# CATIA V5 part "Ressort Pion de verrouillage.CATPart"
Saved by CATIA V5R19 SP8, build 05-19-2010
Part number: Ressort Pion de verrouillage
Bounding box of the stored display mesh (mm): x -1.249 to 1.25, y -1.249 to 1.25, z -0.25 to 6.529
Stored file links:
  C:\Users\Arthur\Desktop\Catia parts\GLOCK\Ensemble culasse\Ressort Pion de verrouillage.CATPart
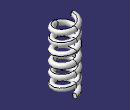
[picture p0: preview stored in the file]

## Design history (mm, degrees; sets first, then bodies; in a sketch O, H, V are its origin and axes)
Set1
  Sketch1 on yz-plane, origin (0, 0, 0), H (0, 1, 0), V (0, 0, 1)
    point P1 (1, 0)
    distance P1 V = 1
  Helix1: Direction Sketch1.V, RefPoint Sketch1, Pitch 1, Height 6.287, TaperAngle 0
  Plane1: type OffsetPt, RefPlane yz-plane, RefPoint Sketch1
  Circle1: type CtrRad, Start 0, End 180, Center Sketch1, Support Plane1, Radius 0.25, FirstDirection (0, 1, 0)
Body1 (main body)
  Rib1: profile Circle1, centre curve Helix1
  Plane2: type Offset, RefPlane xy-plane, Offset 0.3, reversed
